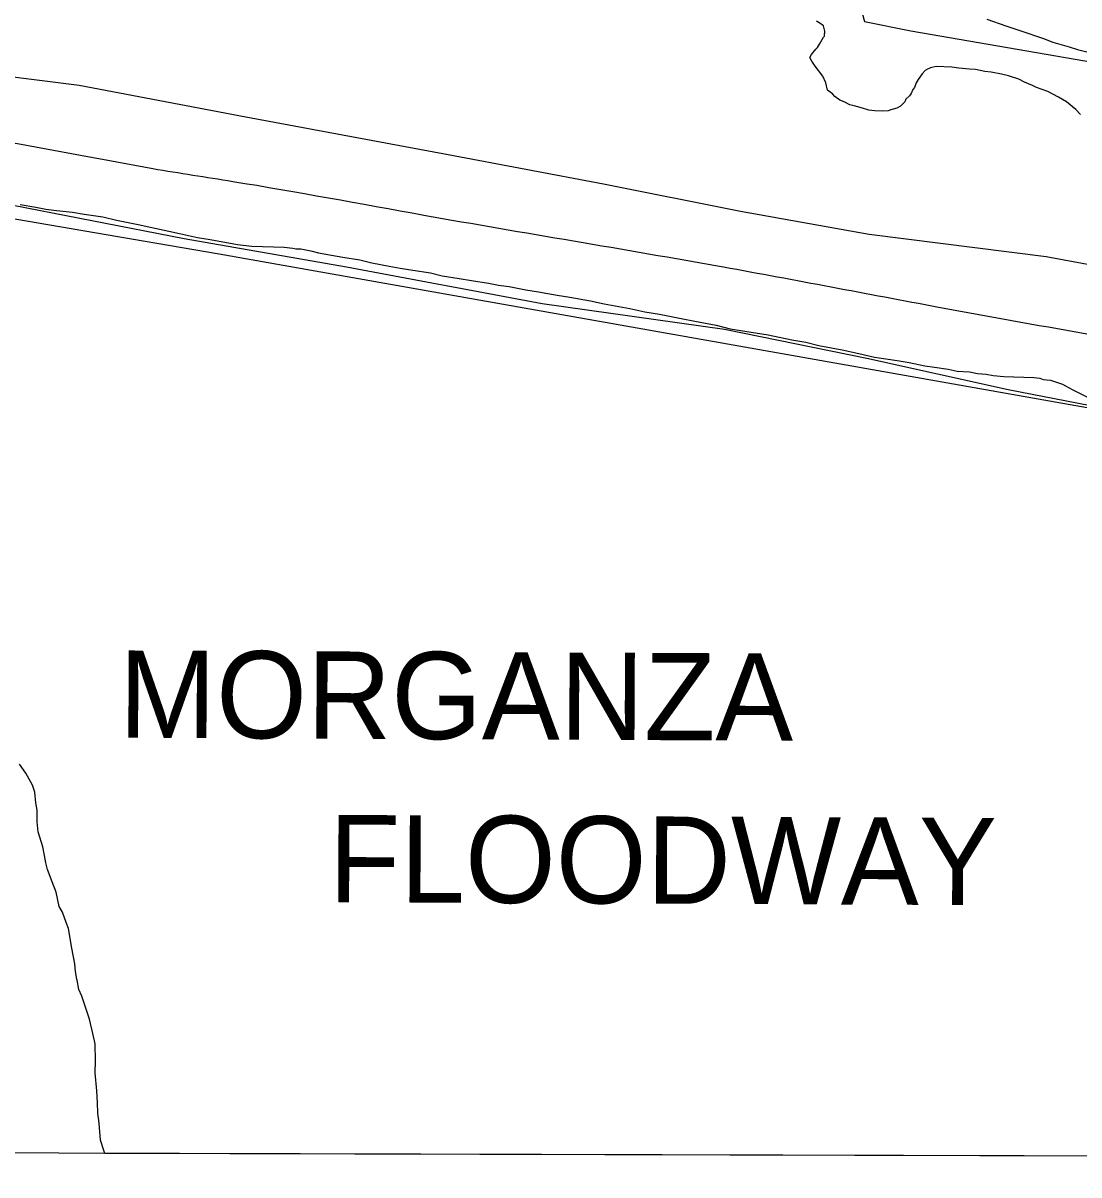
# Model space of a CAD drawing. Extents: x 3161514 to 3199414, y 831166 to 856601.
# Drawn here: x 3182027 to 3184047, y 836546 to 838752 of the extents above; entities that cross this region are included whole.
import ezdxf

# ---------------------------------------------------------------- set-up
doc = ezdxf.new("R2010")
doc.units = 0
for name, color, linetype in [('V-GRID-FRAM', 7, 'Continuous'), ('V-LEVE-TOET', 7, 'Continuous'), ('V-RIVR-IDEN', 7, 'Continuous'), ('V-ROAD-CNTR', 7, 'Continuous'), ('V-SITE-VEGE', 7, 'Continuous'), ('V-TOPO-SHOR', 7, 'Continuous')]:
    doc.layers.add(name, color=color, linetype=linetype)

msp = doc.modelspace()

# ---------------------------------------------------------------- linework, layer by layer
at = {"layer": 'V-GRID-FRAM'}
msp.add_lwpolyline([(3165761, 854820), (3197144.3, 854733.3), (3197102, 836546.1), (3165702.9, 836632.9), (3165761, 854820)], dxfattribs=at)
at = {"layer": 'V-LEVE-TOET'}
for points in [[(3185068.9, 838114.5), (3184960.2, 838139.5), (3184484.1, 838211.7), (3183984.5, 838304.2), (3183645.9, 838346.6), (3183399.7, 838390.5), (3183137.8, 838443.4), (3182840.2, 838499.1), (3182453.2, 838571.5), (3182134.4, 838632), (3181835.3, 838669.5)], [(3185479.9, 837402), (3185378.5, 837572.4), (3185263.2, 837749.1), (3185236.4, 837810.4), (3185224.1, 837829.2), (3185202.7, 837834.6), (3185041.5, 837846.4), (3184746, 837891.8), (3184404.6, 837953.3), (3183911.8, 838049.4), (3183641.4, 838109.2), (3183369.5, 838165.1), (3183020.2, 838213.8), (3182646.2, 838283.9), (3182335, 838338.5), (3181981.1, 838407.4), (3181709.1, 838448.9), (3181476.7, 838488.3), (3181216.9, 838495.2), (3181043.3, 838497.2), (3180895.4, 838492), (3180760.8, 838480.3)]]:
    msp.add_lwpolyline(points, dxfattribs=at)
at = {"layer": 'V-ROAD-CNTR'}
msp.add_spline([(3185247.7, 837950), (3185220.1, 837952.3), (3184919.5, 838004.8), (3184339.6, 838108.5), (3183779, 838207.2), (3183367, 838284.1), (3182794.1, 838383.3), (3182428.7, 838447.8), (3182275.5, 838472.5), (3181998.8, 838523), (3181803.1, 838555.1), (3181641.5, 838586.6), (3181550.7, 838598.2), (3181445.6, 838611.4), (3181325.6, 838620), (3181174.8, 838631.9), (3181016.7, 838639.1), (3180880.4, 838632.5), (3180707.8, 838613), (3180579.6, 838596.6), (3180431.4, 838569.9), (3180332.4, 838547.3), (3180171.1, 838506.1), (3180026.7, 838458.9), (3179877.5, 838403.8), (3179654.2, 838294.6), (3179462.8, 838196.9), (3179346.3, 838121.9), (3179173.3, 838003.7), (3178965.2, 837857.6), (3178757.9, 837712.7), (3178391.8, 837460.5), (3178085.3, 837254.5), (3177675.2, 836977.6), (3177220.5, 836675.6), (3177123, 836609.3)], degree=3, dxfattribs=at)
at = {"layer": 'V-SITE-VEGE'}
for p, q in [((3182021.3, 838404), (3182051.2, 838399)), ((3182051.2, 838399), (3182070.5, 838395.3)), ((3182070.5, 838395.3), (3182090.8, 838392.6)), ((3182090.8, 838392.6), (3182121.8, 838389.4)), ((3182121.8, 838389.4), (3182144, 838385.7)), ((3182144, 838385.7), (3182179.8, 838380.4)), ((3182179.8, 838380.4), (3182205.8, 838374.5)), ((3182205.8, 838374.5), (3182247.3, 838366.1)), ((3182247.3, 838366.1), (3182273.3, 838360.2)), ((3182273.3, 838360.2), (3182306.1, 838353.1)), ((3182306.1, 838353.1), (3182326.4, 838348.4)), ((3182326.4, 838348.4), (3182361.1, 838341.2)), ((3182361.1, 838341.2), (3182385.2, 838337.4)), ((3182385.2, 838337.4), (3182437.4, 838327.6)), ((3182437.4, 838327.6), (3182464.5, 838324.6)), ((3182464.5, 838324.6), (3182526.6, 838322.2)), ((3182526.6, 838322.2), (3182543.1, 838320.5)), ((3182543.1, 838320.5), (3182548.9, 838319.3)), ((3182548.9, 838319.3), (3182558.6, 838319)), ((3182558.6, 838319), (3182577.9, 838315.3)), ((3182577.9, 838315.3), (3182592.3, 838311.8)), ((3182592.3, 838311.8), (3182617.4, 838307)), ((3182617.4, 838307), (3182638.6, 838303.2)), ((3182638.6, 838303.2), (3182671.5, 838298)), ((3182671.5, 838298), (3182694.6, 838292.3)), ((3182694.6, 838292.3), (3182727.4, 838286.1)), ((3182727.4, 838286.1), (3182748.7, 838282.4)), ((3182748.7, 838282.4), (3182772.8, 838278.5)), ((3182772.8, 838278.5), (3182806.7, 838273.3)), ((3182806.7, 838273.3), (3182828.8, 838267.6)), ((3182828.8, 838267.6), (3182861.7, 838262.4)), ((3182861.7, 838262.4), (3182884.9, 838258.6)), ((3182884.9, 838258.6), (3182917.7, 838253.5)), ((3182917.7, 838253.5), (3182937, 838249.8)), ((3182937, 838249.8), (3182957.3, 838247.1)), ((3182957.3, 838247.1), (3182989.2, 838241)), ((3182989.2, 838241), (3183013.3, 838237.1)), ((3183013.3, 838237.1), (3183049.1, 838230.8)), ((3183049.1, 838230.8), (3183073.2, 838227)), ((3183073.2, 838227), (3183112.8, 838219.6)), ((3183112.8, 838219.6), (3183138.8, 838213.7)), ((3183138.8, 838213.7), (3183188.1, 838205)), ((3183188.1, 838205), (3183217, 838199)), ((3183217, 838199), (3183245, 838194.1)), ((3183245, 838194.1), (3183286.5, 838185.6)), ((3183286.5, 838185.6), (3183312.6, 838180.7)), ((3183312.6, 838180.7), (3183353.1, 838173.3)), ((3183353.1, 838173.3), (3183380.1, 838166.4)), ((3183380.1, 838166.4), (3183408.1, 838161.5)), ((3183408.1, 838161.5), (3183452.5, 838154.9)), ((3183452.5, 838154.9), (3183497.9, 838145.3)), ((3183497.9, 838145.3), (3183524.9, 838140.4)), ((3183524.9, 838140.4), (3183549.9, 838134.5)), ((3183549.9, 838134.5), (3183594.3, 838126)), ((3183594.3, 838126), (3183626.1, 838118.9)), ((3183626.1, 838118.9), (3183656, 838111.9)), ((3183656, 838111.9), (3183699.5, 838105.4)), ((3183699.5, 838105.4), (3183722.7, 838101.6)), ((3183722.7, 838101.6), (3183752.6, 838095.5)), ((3183752.6, 838095.5), (3183771, 838092.9)), ((3183771, 838092.9), (3183797.1, 838089)), ((3183797.1, 838089), (3183814.4, 838085.4)), ((3183814.4, 838085.4), (3183837.7, 838083.5)), ((3183837.7, 838083.5), (3183853.2, 838080.9)), ((3183853.2, 838080.9), (3183869.6, 838079.3)), ((3183869.6, 838079.3), (3183883.1, 838076.9)), ((3183883.1, 838076.9), (3183903.5, 838075.1)), ((3183903.5, 838075.1), (3183960.8, 838072.9)), ((3183960.8, 838072.9), (3183972.4, 838071.4)), ((3183972.4, 838071.4), (3183979.1, 838069.2)), ((3183979.1, 838069.2), (3183992.7, 838067.7)), ((3183992.7, 838067.7), (3184002.3, 838064.4)), ((3184002.3, 838064.4), (3184015.7, 838060)), ((3184015.7, 838060), (3184021.4, 838056.9)), ((3184021.4, 838056.9), (3184035.7, 838049.5)), ((3184035.7, 838049.5), (3184084.3, 838025.3)), ((3182032.4, 837315.6), (3182020.4, 837332.6)), ((3182045.1, 837292.7), (3182032.4, 837315.6)), ((3182049.4, 837279), (3182045.1, 837292.7)), ((3182051.6, 837258.5), (3182049.4, 837279)), ((3182053.9, 837244.8), (3182051.6, 837258.5)), ((3182054, 837222.4), (3182053.9, 837244.8)), ((3182056.2, 837202.9), (3182054, 837222.4)), ((3182064.8, 837174.3), (3182056.2, 837202.9)), ((3182068.1, 837157.7), (3182064.8, 837174.3)), ((3182070.4, 837144), (3182068.1, 837157.7)), ((3182073.8, 837131.2), (3182070.4, 837144)), ((3182082.6, 837107.5), (3182073.8, 837131.2)), ((3182090.6, 837087.8), (3182082.6, 837107.5)), ((3182096.4, 837060.3), (3182090.6, 837087.8)), ((3182102.7, 837049.4), (3182096.4, 837060.3)), ((3182109.8, 837029.7), (3182102.7, 837049.4)), ((3182114.2, 837017.8), (3182109.8, 837029.7)), ((3182120.5, 836980.6), (3182114.2, 837017.8)), ((3182126.1, 836950.3), (3182120.5, 836980.6)), ((3182127.5, 836935.6), (3182126.1, 836950.3)), ((3182129.8, 836920.9), (3182127.5, 836935.6)), ((3182130.7, 836919), (3182129.8, 836920.9)), ((3182133.9, 836901.3), (3182130.7, 836919)), ((3182139.3, 836888.5), (3182133.9, 836901.3)), ((3182148, 836863.8), (3182139.3, 836888.5)), ((3182154.1, 836844.2), (3182148, 836863.8)), ((3182160.8, 836816.7), (3182154.1, 836844.2)), ((3182164.9, 836797.1), (3182160.8, 836816.7)), ((3182165.5, 836764), (3182164.9, 836797.1)), ((3182164.7, 836741.7), (3182165.5, 836764)), ((3182168.2, 836707.5), (3182164.7, 836741.7)), ((3182169.3, 836685.1), (3182168.2, 836707.5)), ((3182170.4, 836664.6), (3182169.3, 836685.1)), ((3182172.6, 836645.1), (3182170.4, 836664.6)), ((3182175.2, 836612.9), (3182172.6, 836645.1)), ((3182182.1, 836591.2), (3182175.2, 836612.9)), ((3182183.6, 836587.3), (3182182.1, 836591.2)), ((3184917.8, 836579.8), (3182183.6, 836587.3))]:
    msp.add_line(p, q, dxfattribs=at)
for points in [[(3183871, 838759.1), (3183907.5, 838746.1), (3183934.3, 838737.2), (3183979.4, 838721.9), (3183997.7, 838715.3)], [(3184050.6, 838576.2), (3184041.3, 838586.2), (3184023.3, 838600.6), (3184008.1, 838609.9), (3183988.1, 838620.4), (3183966.1, 838628.1), (3183958.5, 838632.3), (3183943.1, 838638.7), (3183932.7, 838644), (3183912.5, 838650.6), (3183899, 838654), (3183879.7, 838657.7), (3183867.1, 838659.1), (3183849.8, 838662.7), (3183838.1, 838663.2), (3183817.8, 838664.9), (3183804.3, 838667.4), (3183774.2, 838668.6), (3183763.4, 838666.1), (3183757.4, 838663.4), (3183753.4, 838660.6), (3183747.3, 838654.1), (3183740.1, 838643.7), (3183736, 838637), (3183732.7, 838628.4), (3183729.7, 838624.6), (3183726.5, 838617), (3183723.3, 838612.2), (3183716.3, 838605.7), (3183714.2, 838600.9), (3183706.1, 838592.5), (3183699.1, 838588.9), (3183687.3, 838585.4), (3183682.4, 838583.7), (3183671.7, 838583.1), (3183657.1, 838583.7), (3183645.5, 838585.1), (3183633, 838588.5), (3183617.6, 838593), (3183608.9, 838595.3), (3183598.4, 838600.6), (3183589.8, 838603.8), (3183580.4, 838611), (3183575.7, 838616), (3183569.1, 838621.1), (3183566.3, 838623.2), (3183562.9, 838636.9), (3183557.6, 838649.8), (3183542.8, 838668.8), (3183536.3, 838678.8), (3183532.7, 838685.8), (3183535.9, 838691.5), (3183544, 838701.9), (3183547.1, 838704.7), (3183551.2, 838711.3), (3183558.5, 838724.6), (3183560.6, 838726.5), (3183560.9, 838736.2), (3183558.4, 838746), (3183551.8, 838751.1), (3183545.1, 838755.3)], [(3183997.7, 838715.3), (3184028.4, 838706.3), (3184044.7, 838700.8), (3184067.9, 838695.1)]]:
    msp.add_lwpolyline(points, dxfattribs=at)
at = {"layer": 'V-TOPO-SHOR'}
for points in [[(3183637.2, 840383.1), (3183482.4, 839790.5), (3184071.1, 839502.7), (3184186.2, 839343.4), (3184314.6, 839223.9), (3184460.6, 838945), (3184442.9, 838798.9), (3184376.5, 838807.8), (3184336.7, 838785.7), (3183597.5, 838896.3), (3183637.3, 838754.7), (3183725.8, 838737), (3184673.1, 838573.2)], [(3180751.3, 838473.6), (3181118.7, 838469.2), (3181428.6, 838469.2), (3181627.7, 838442.6), (3182141.2, 838354.1), (3182402.4, 838309.8), (3184124.2, 838004.4), (3184190.6, 837969), (3184310.1, 837924.7), (3184367.7, 837902.6), (3184407.5, 837853.9), (3184438.5, 837818.5), (3184863.4, 837765.4), (3184952, 837796.4), (3185137.9, 837787.5), (3185093.6, 837880.5)]]:
    msp.add_lwpolyline(points, dxfattribs=at)

# ---------------------------------------------------------------- texts
at = {"layer": 'V-RIVR-IDEN'}
for s, p in [('MORGANZA', (3182210.2, 837383.4)), ('FLOODWAY', (3182611.7, 837068.5))]:
    msp.add_text(s, height=167, rotation=359.7335, dxfattribs=at).set_placement(p)

doc.saveas('drawing.dxf')
